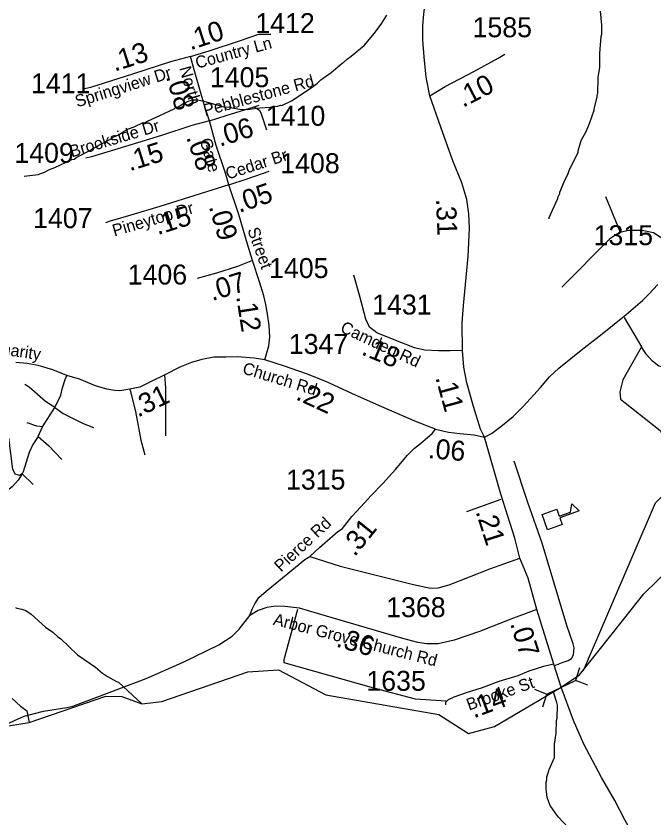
# Model space of a CAD drawing. Extents: x 1248224 to 1454986, y 825081 to 985870.
# Drawn here: x 1334606 to 1338598, y 899816 to 904837 of the extents above; entities that cross this region are included whole.
import ezdxf

# ---------------------------------------------------------------- set-up
doc = ezdxf.new("R2010")
doc.units = 0
for name, color, linetype in [('Exist Cultural Educational Facility High CELL', 7, 'Continuous'), ('Exist Hydrographic Creek Single Shore', 7, 'Continuous'), ('Exist Hydrographic Misc Water Feature', 7, 'Continuous'), ('Exist Road Non-System Type 51', 7, 'Continuous'), ('Exist Road Primary NC Attributed', 7, 'Continuous'), ('Exist Road Primary NC Mileage Hundredths English Label', 7, 'Continuous'), ('Exist Road Primary NC Structure Culvert CELL', 7, 'Continuous'), ('Exist Road Primary NC Structure Culvert Number Label', 7, 'Continuous'), ('Exist Road Secondary Mileage Hundredths English Label', 7, 'Continuous'), ('Exist Road Secondary Type 51 Attributed', 7, 'Continuous'), ('Exist Road Secondary Type 51 Label', 7, 'Continuous'), ('Exist Road Secondary Type 51 Number Label', 7, 'Continuous')]:
    doc.layers.add(name, color=color, linetype=linetype)

msp = doc.modelspace()

# ---------------------------------------------------------------- linework, layer by layer
at = {"layer": 'Exist Cultural Educational Facility High CELL'}
msp.add_lwpolyline([(1337897.4, 901716.1), (1337989.8, 901748.5), (1338005.1, 901705.1), (1338075.9, 901729.9), (1338083.3, 901782.3), (1338129.5, 901738.5), (1338008.2, 901696), (1338023.4, 901652.5), (1337931, 901620.2)], close=True, dxfattribs=at)
at = {"layer": 'Exist Hydrographic Creek Single Shore'}
for points in [[(1338336.5, 900969.2), (1338535.5, 901219.7), (1338790.5, 901470.6)], [(1337438.1, 900343.7), (1337599.4, 900388.1), (1338016.6, 900635.6), (1338132.5, 900712.4), (1338336.5, 900969.2)]]:
    msp.add_lwpolyline(points, dxfattribs=at)
at = {"layer": 'Exist Hydrographic Misc Water Feature'}
for points in [[(1336328.6, 904305.5), (1336459.6, 904390.7), (1336492.2, 904415.9), (1336512.7, 904437.5), (1336577.7, 904484), (1336647, 904542.5), (1336655.1, 904546.3), (1336679.6, 904569.7), (1336703.9, 904585.1), (1336783.4, 904651.3), (1336849.2, 904729.9), (1336894.6, 904792.8), (1336925.6, 904842)], [(1337941.5, 903566.9), (1337941.6, 903574.9), (1337996.2, 903693.7), (1337996.4, 903701.6), (1338008.9, 903725.3), (1338009.1, 903733.3), (1338042.9, 903812.6), (1338059.6, 903844.2), (1338068.3, 903875.9), (1338122.6, 903982.8), (1338122.5, 903992.4), (1338142.3, 904056.6), (1338173.6, 904113.6), (1338194.7, 904163.1), (1338224.5, 904248.4), (1338225, 904264.4), (1338242.3, 904328), (1338242.7, 904344), (1338246.9, 904351.9), (1338248.4, 904453.9), (1338258.5, 904515.6), (1338258.8, 904602.6), (1338266.8, 904709.5), (1338271.1, 904723.3), (1338272.3, 904779.3), (1338262.3, 904867.6)], [(1334656, 903833.6), (1334743.4, 903844.3), (1334783.8, 903859.1), (1334814.2, 903876.3), (1334848.7, 903889.2), (1334954.1, 903938.2), (1334970.2, 903941.7), (1334986.5, 903953.2), (1335075.9, 903998.6), (1335084.1, 904006.4), (1335108.4, 904017.6), (1335124.7, 904029.2), (1335205.9, 904070.8), (1335214.2, 904078.6), (1335246.6, 904093.6), (1335303.6, 904128), (1335344, 904142.8), (1335400.8, 904169.2), (1335408.8, 904169), (1335425, 904176.4), (1335595.3, 904255.5), (1335603.5, 904263.3), (1335619.7, 904268.8), (1335656.4, 904291.7), (1335688.8, 904306.8), (1335717, 904312), (1335741, 904311.3), (1335772.8, 904306.3), (1335899.9, 904270.7), (1335931.8, 904265.7), (1335939.7, 904267.6), (1335955.6, 904261.1), (1336003.4, 904253.9), (1336051.4, 904251.9), (1336131.7, 904261.3), (1336196, 904266.1), (1336212.1, 904270.6), (1336244.3, 904272.8), (1336260.5, 904278.5), (1336268.3, 904277.5), (1336328.6, 904305.5)], [(1334602.5, 901133.3), (1334610.4, 901129.1), (1334642.3, 901124.1), (1334666.1, 901115.4), (1334701.4, 901092.4), (1334791.2, 901009.8), (1334836.3, 900978.6), (1334865.6, 900951.7), (1334887.1, 900937), (1334990.4, 900836.2), (1335102.2, 900759), (1335147.2, 900721.6), (1335178.6, 900700.7), (1335233.9, 900671.1), (1335247.7, 900666.8), (1335392.4, 900531)], [(1332415.3, 898397.8), (1332865.4, 899120.8), (1333666.3, 900178.2), (1333910.3, 900288.2), (1334688.4, 900413.8), (1335168.3, 900578.2), (1335268.4, 900576.1), (1335392.4, 900531), (1335517.4, 900544.9), (1336055.4, 900731.1), (1336248.5, 900743.6)], [(1336248.5, 900743.6), (1336545.4, 900586.6), (1337251.5, 900464.2), (1337438.1, 900343.7)], [(1334582.5, 900564), (1334633.3, 900516.6), (1334672.4, 900487.5), (1334688.4, 900413.8)], [(1338092.3, 899723.4), (1338000.5, 899821.6), (1337981, 899846), (1337948.1, 899894.8), (1337929.2, 899943.1), (1337922.4, 899999.3), (1337923.3, 900039.3), (1337927.6, 900055.2), (1337928, 900073.1), (1337940.9, 900110.9), (1337941.1, 900118.9), (1337974.7, 900194.1), (1337974.9, 900277.1), (1337986.1, 900345.9), (1337987.9, 900425.8), (1337992.2, 900441.7), (1337994, 900521.7), (1337990.4, 900537.8), (1337969.9, 900603.2)]]:
    msp.add_lwpolyline(points, dxfattribs=at)
at = {"layer": 'Exist Road Non-System Type 51'}
for p, q in [((1338294.4, 903706.4), (1338386.1, 903483.8)), ((1338411.3, 902949.2), (1338519.1, 902765.6)), ((1334644.5, 901970.4), (1334712.7, 901903.8)), ((1337426.2, 901734.6), (1337641.9, 901811.5))]:
    msp.add_line(p, q, dxfattribs=at)
for points in [[(1336095.9, 904268), (1336128.8, 904247.6), (1336138.8, 904225), (1336174.1, 904124.2)], [(1338386.1, 903483.8), (1338321.9, 903442.5), (1338021.5, 903139.6)], [(1338386.1, 903483.8), (1338438.8, 903495.3), (1338523.7, 903495.3), (1338594.8, 903481.5), (1338762.1, 903373.7)], [(1338519.1, 902765.6), (1338402.1, 902559), (1338383.8, 902483.3), (1338388.4, 902437.4), (1338418.2, 902414.5), (1338636, 902242.4), (1338656.7, 902201.1), (1338684.2, 902095.5), (1338730, 901939.5), (1338753, 901875.2), (1338769, 901843.1), (1338794.2, 901822.4), (1338853.9, 901811), (1339168, 901817.8), (1339234.5, 901843.1), (1339284.9, 901872.9), (1339333.1, 901923.4), (1339369.8, 901967), (1339429.4, 901992.2)], [(1338977.7, 902253.8), (1338897.4, 902522.3), (1338872.2, 902584.3), (1338835.5, 902609.5), (1338801.1, 902618.7), (1338746.1, 902623.3), (1338681.9, 902632.5), (1338629.2, 902644), (1338587.9, 902676.1), (1338548.9, 902719.7), (1338519.1, 902765.6)], [(1334848.5, 902384.8), (1334886, 902462.6), (1334895.7, 902508.5), (1334912.4, 902561.3), (1334924.6, 902585.4)], [(1335543.2, 902208.4), (1335543.2, 902352.9), (1335543.2, 902507.1), (1335536.7, 902590)], [(1334848.5, 902384.8), (1334790.2, 902422.4), (1334687.5, 902512.7), (1334661.1, 902530.7)], [(1335317.3, 902499.9), (1335353, 902359.8), (1335387.7, 902180.6), (1335411.3, 902090.3)], [(1334770.8, 902264), (1334848.5, 902384.8)], [(1334848.5, 902384.8), (1334901.3, 902348.7), (1335026.2, 902286.2), (1335090.1, 902259.8)], [(1334770.8, 902264), (1334736.1, 902269.5), (1334676.4, 902289)], [(1334744.4, 902204.3), (1334770.8, 902264)], [(1334644.5, 901970.4), (1334627.5, 901961.1), (1334599.6, 901968.9), (1334585.6, 901999.9), (1334560.9, 902195.2)], [(1334744.4, 902204.3), (1334711.1, 902153.4), (1334687.9, 902103.8), (1334650.7, 901982.8), (1334644.5, 901970.4)], [(1334744.4, 902204.3), (1334811, 902145.9), (1334892.9, 902061.2)], [(1337976.8, 900771.4), (1338029.5, 900790.9), (1338060.5, 900801.3), (1338081.1, 900815), (1338093.7, 900838), (1338097.2, 900860.9), (1338098.3, 900880.4), (1338091.4, 900906.8), (1338053.6, 901020.4), (1337898.5, 901537.2), (1337809.3, 901790.1), (1337723.1, 902048.9)], [(1334644.5, 901970.4), (1334618.2, 901930.1), (1334584.1, 901891.4), (1334429.2, 901768.9)], [(1336444.8, 901453.9), (1336635.1, 901391.5), (1337092.9, 901278.4), (1337199.9, 901254.6), (1337247.5, 901257.6), (1337315.8, 901275.4), (1337571.5, 901376.6), (1337758.8, 901442)], [(1337296.9, 900547.7), (1337106.6, 900559.2), (1336845.2, 900628), (1336283.4, 900786.3), (1336283.4, 900807), (1336368.3, 901123.7)]]:
    msp.add_lwpolyline(points, dxfattribs=at)
at = {"layer": 'Exist Road Primary NC Attributed'}
for points in [[(1337195.2, 904338.2), (1337171.9, 904454.9), (1337160, 904580.7), (1337152, 904687.3), (1337152, 904777.2), (1337157.9, 904849.1), (1337171.9, 904972.9), (1337201.8, 905116.6), (1337255.5, 905345), (1337261.5, 905430.9), (1337259.5, 905528.7), (1337253.6, 905612.6), (1337245.6, 905666.5), (1337229.6, 905722.4), (1337211.7, 905782.3), (1337164.2, 905863.2), (1337076.5, 905998.9), (1336942.8, 906202.6), (1336879, 906334.4), (1336761.2, 906593.9), (1336661.4, 906814.7)], [(1337400.2, 902742.6), (1337396.6, 902916.1), (1337405.9, 903025), (1337435.7, 903332), (1337443.1, 903507.8), (1337439.4, 903599), (1337426.4, 903688.3), (1337394.8, 903792.5), (1337339, 903930.2), (1337264.6, 904140.4), (1337195.2, 904338.2)], [(1337537.7, 902199.2), (1337513.3, 902250), (1337468.6, 902392), (1337427.8, 902539.8), (1337408.4, 902639), (1337400.2, 902742.6)], [(1337864, 901122), (1337810.4, 901317.5), (1337758.8, 901442), (1337727.3, 901566.8), (1337639.1, 901843.7), (1337537.7, 902199.2)], [(1337971.3, 900777.8), (1337864, 901122)], [(1339042.5, 898569.9), (1338819.4, 899030), (1338710.4, 899237.7), (1338560.2, 899513.8), (1338451.3, 899738.8), (1338418.5, 899800), (1338352.9, 899924.9), (1338269.9, 900068.6), (1338159.2, 900278), (1338093.7, 900426.1), (1338016.6, 900635.6), (1337971.3, 900777.8)]]:
    msp.add_lwpolyline(points, dxfattribs=at)
at = {"layer": 'Exist Road Primary NC Structure Culvert CELL'}
for p, q in [((1338132.6, 900755.5), (1338106.8, 900676.3)), ((1337927.6, 900591.2), (1338106.8, 900676.3)), ((1338184.5, 900646.3), (1338106.8, 900676.3)), ((1337850, 900621.3), (1337927.6, 900591.2)), ((1337901.8, 900512), (1337927.6, 900591.2))]:
    msp.add_line(p, q, dxfattribs=at)
at = {"layer": 'Exist Road Primary NC Structure Culvert Number Label'}
msp.add_lwpolyline([(1338157.3, 900739.9), (1338606.8, 901788.8), (1339156.3, 902338.2)], dxfattribs=at)
at = {"layer": 'Exist Road Secondary Type 51 Attributed'}
for points in [[(1335697.7, 904582.6), (1335814.3, 904619.5), (1336004.8, 904681.8), (1336125.3, 904722.6), (1336200.9, 904722.4)], [(1335697.7, 904582.6), (1335573.2, 904549.3), (1335334.1, 904473.4), (1335157.2, 904417), (1335071.7, 904389.8), (1335036.7, 904380.1)], [(1335816, 904180.5), (1335787.1, 904267.5), (1335721, 904500.9), (1335697.7, 904582.6)], [(1337195.2, 904338.2), (1337290.4, 904396.1), (1337469.7, 904489.6), (1337622.8, 904573.7), (1337663.6, 904597.2)], [(1335816, 904180.5), (1335921, 904213.6), (1336095.9, 904268), (1336128.2, 904278.1)], [(1335816, 904180.5), (1335705.2, 904151.3), (1335516.7, 904089.1), (1335291.2, 904019.1), (1335077.4, 903954.9), (1335042.5, 903947.1)], [(1335938.2, 903779.4), (1335917.1, 903853.7), (1335858.8, 904026.8), (1335816, 904180.5)], [(1335938.2, 903779.4), (1336051.2, 903817.7), (1336190.7, 903864.8)], [(1335938.2, 903779.4), (1335757.7, 903724.3), (1335505.1, 903644.5), (1335324.3, 903590.1), (1335194.1, 903553.1), (1335165.8, 903541.6)], [(1336085.5, 903305.9), (1336054.8, 903407.9), (1336000.4, 903594.6), (1335938.2, 903779.4)], [(1336085.5, 903305.9), (1335992.6, 903268.4), (1335860.4, 903227.5), (1335739.9, 903192.5)], [(1336163.1, 902683.8), (1336188.6, 902770.9), (1336194.4, 902827.4), (1336190.5, 902899.3), (1336178.8, 902969.4), (1336169.1, 903031.6), (1336157.5, 903084.1), (1336130.3, 903171.7), (1336085.5, 903305.9)], [(1337400.2, 902742.6), (1337322.4, 902740.6), (1337248.6, 902740.6), (1337165, 902744.5), (1337098.9, 902760.1), (1336972.6, 902808.7), (1336863.7, 902853.5), (1336817.1, 902888.5), (1336795.7, 902939), (1336754.9, 903088.8), (1336719.9, 903215.3)], [(1337537.7, 902199.2), (1337580.5, 902222.6), (1337638.8, 902267.3), (1337716.5, 902329.6), (1337780.5, 902393.3), (1337887.4, 902511.9), (1337943.7, 902578.1), (1338002.1, 902632.5), (1338142, 902745.4), (1338273.3, 902847.6), (1338422.9, 902968.2), (1338525.9, 903055.8), (1338564.8, 903094.7), (1338621.2, 903156.9)], [(1336163.1, 902683.8), (1336095.6, 902694), (1335989.3, 902703.3), (1335917.7, 902701), (1335843.8, 902701), (1335767.6, 902687.1), (1335703, 902668.6), (1335631.4, 902638.6), (1335536.7, 902590), (1335451.2, 902548.4), (1335379.6, 902513.7), (1335317.3, 902499.9), (1335254.9, 902490.6), (1335224.9, 902492.9), (1335174.1, 902499.9), (1335102.5, 902520.7), (1335003.2, 902562.3), (1334924.6, 902585.4), (1334836.9, 902622.4), (1334744.5, 902647.8), (1334675.2, 902661.7), (1334603.6, 902668.6)], [(1337230.6, 902249.8), (1337111.6, 902296.7), (1336895.9, 902390.1), (1336730.6, 902462.1), (1336544.1, 902547.7), (1336423.5, 902596.3), (1336285.5, 902644.9), (1336163.1, 902683.8)], [(1336069.5, 901082.6), (1336083.3, 901124), (1336099.4, 901156.2), (1336124.7, 901195.4), (1336170.7, 901236.8), (1336273.3, 901318.7), (1336413.5, 901433.7), (1336444.8, 901453.9), (1336505.5, 901509.6), (1336620.4, 901608.5), (1336648, 901629.2), (1336707.8, 901702.8), (1336762.9, 901764.9), (1336827.3, 901834), (1336900.9, 901909.9), (1336981.3, 901997.3), (1337054.9, 902087), (1337098.5, 902130.7), (1337137.6, 902160.6), (1337181.3, 902197.4), (1337208.9, 902222.7), (1337230.6, 902249.8)], [(1337230.6, 902249.8), (1337312.3, 902230.4), (1337382.2, 902222.6), (1337473.6, 902214.8), (1337537.7, 902199.2)], [(1337864, 901122), (1337841, 901112.8), (1337703.1, 901059.9), (1337505.4, 900984), (1337346.8, 900928.8), (1337248, 900905.8), (1337176.7, 900905.8), (1337119.3, 900915), (1337027.3, 900940.3), (1336756.1, 901018.5), (1336549.2, 901078.3), (1336379.1, 901128.9), (1336287.2, 901140.4), (1336229.7, 901142.7), (1336174.6, 901133.5), (1336121.7, 901115.1), (1336069.5, 901082.6)], [(1333164, 899764.8), (1333223.9, 899816.3), (1333283.9, 899861.4), (1333365.4, 899904.2), (1333453.2, 899949.3), (1333603.2, 900009.3), (1333876.4, 900109.5), (1334202.1, 900240.3), (1334322.1, 900298.2), (1334517.1, 900388.3), (1334596.4, 900426.9), (1334656.4, 900452.6), (1334778.5, 900484.8), (1334924.3, 900508.4), (1334961.9, 900516.2), (1335094.8, 900565.5), (1335420.5, 900689.9), (1335647, 900790.2), (1335874.2, 900899.6), (1335957.7, 900953.2), (1336002.7, 900998.2), (1336069.5, 901082.6)], [(1337971.3, 900777.8), (1337906.9, 900764), (1337815, 900734.1), (1337746, 900706.5), (1337626.5, 900669.7), (1337523, 900630.6), (1337421.9, 900598.4), (1337346, 900573.1), (1337309.3, 900554.7), (1337293.2, 900538.6), (1337293.2, 900524.8)]]:
    msp.add_lwpolyline(points, dxfattribs=at)

# ---------------------------------------------------------------- texts
at = {"layer": 'Exist Road Primary NC Mileage Hundredths English Label'}
for s, rotation, p in [('.31', 272.3354, (1337233.9, 903691.3)), ('.11', 285.4346, (1337229.1, 902573.3)), ('.21', 287.6665, (1337480.6, 901733.6)), ('.07', 287.3035, (1337696.4, 901033.7))]:
    msp.add_text(s, height=125, rotation=rotation, dxfattribs=at).set_placement(p)
at = {"layer": 'Exist Road Secondary Mileage Hundredths English Label'}
for s, rotation, p in [('.10', 18.0968, (1335696.5, 904621.7)), ('.13', 17.6055, (1335222.3, 904488.3)), ('.08', 285.8075, (1335543.2, 904459.5)), ('.10', 27.5305, (1337402.3, 904261.1)), ('.06', 17.2944, (1335880.9, 904017.8)), ('.08', 288.6143, (1335669.8, 904077.8)), ('.15', 17.2542, (1335316.8, 903864.3)), ('.05', 18.6553, (1336002.3, 903603.7)), ('.15', 17.5174, (1335491.7, 903464.5)), ('.09', 286.248, (1335811.8, 903643.5)), ('.07', 17.1747, (1335832.6, 903051.8)), ('.12', 278.8734, (1335983, 903081)), ('.18', 337.6553, (1336761, 902719.2)), ('.31', 25.8382, (1335368.3, 902321.6)), ('.22', 335.3594, (1336350.3, 902439.1)), ('.06', 355.1318, (1337180.8, 902069.3)), ('.31', 50.9281, (1336724.5, 901447.1)), ('.36', 343.9144, (1336603, 900890.4)), ('.14', 20.7106, (1337470, 900438.6))]:
    msp.add_text(s, height=125, rotation=rotation, dxfattribs=at).set_placement(p)
at = {"layer": 'Exist Road Secondary Type 51 Label'}
for s, rotation, p in [('Country Ln', 15.3765, (1335739.8, 904506.5)), ('North        Gate', 285.884, (1335626.4, 904511.2)), ('Springview Dr', 17.38, (1334989, 904264.8)), ('Pebblestone Rd', 15.4164, (1335789.7, 904208.8)), ('Brookside Dr', 16.8264, (1334954.7, 903951)), ('Cedar Br', 18.0846, (1335931.2, 903811.8)), ('Pineytop Dr', 16.3566, (1335220.9, 903455.9)), ('Street', 289.7412, (1336052.6, 903498.5)), ('Camden Rd', 334.7891, (1336629.3, 902862.4)), ('Charity ', 351.602, (1334441.5, 902728.1)), ('Church Rd', 342.9821, (1336017.4, 902600.3)), ('Pierce Rd', 43.0246, (1336263.7, 901352)), ('Arbor Grove Church Rd', 345.562, (1336210.3, 901026.4)), ('Brooke St', 19.5012, (1337440.3, 900487.4))]:
    msp.add_text(s, height=75, rotation=rotation, dxfattribs=at).set_placement(p)
at = {"layer": 'Exist Road Secondary Type 51 Number Label'}
for s, p in [('1412', (1336103.1, 904729.9)), ('1585', (1337462.8, 904704)), ('1411', (1334699.5, 904352.9)), ('1405', (1335818.9, 904391.3)), ('1410', (1336169.3, 904149.8)), ('1409', (1334595.4, 903917.4)), ('1408', (1336259.4, 903852.8)), ('1407', (1334712.5, 903509)), ('1315', (1338220.2, 903402.2)), ('1405', (1336189.4, 903196.4)), ('1406', (1335304.7, 903155.8)), ('1431', (1336834.6, 902967.9)), ('1347', (1336312.8, 902721.2)), ('1315', (1336295.2, 901871.8)), ('1368', (1336922.1, 901073)), ('1635', (1336798.1, 900612))]:
    msp.add_text(s, height=125, dxfattribs=at).set_placement(p)

doc.saveas('drawing.dxf')
